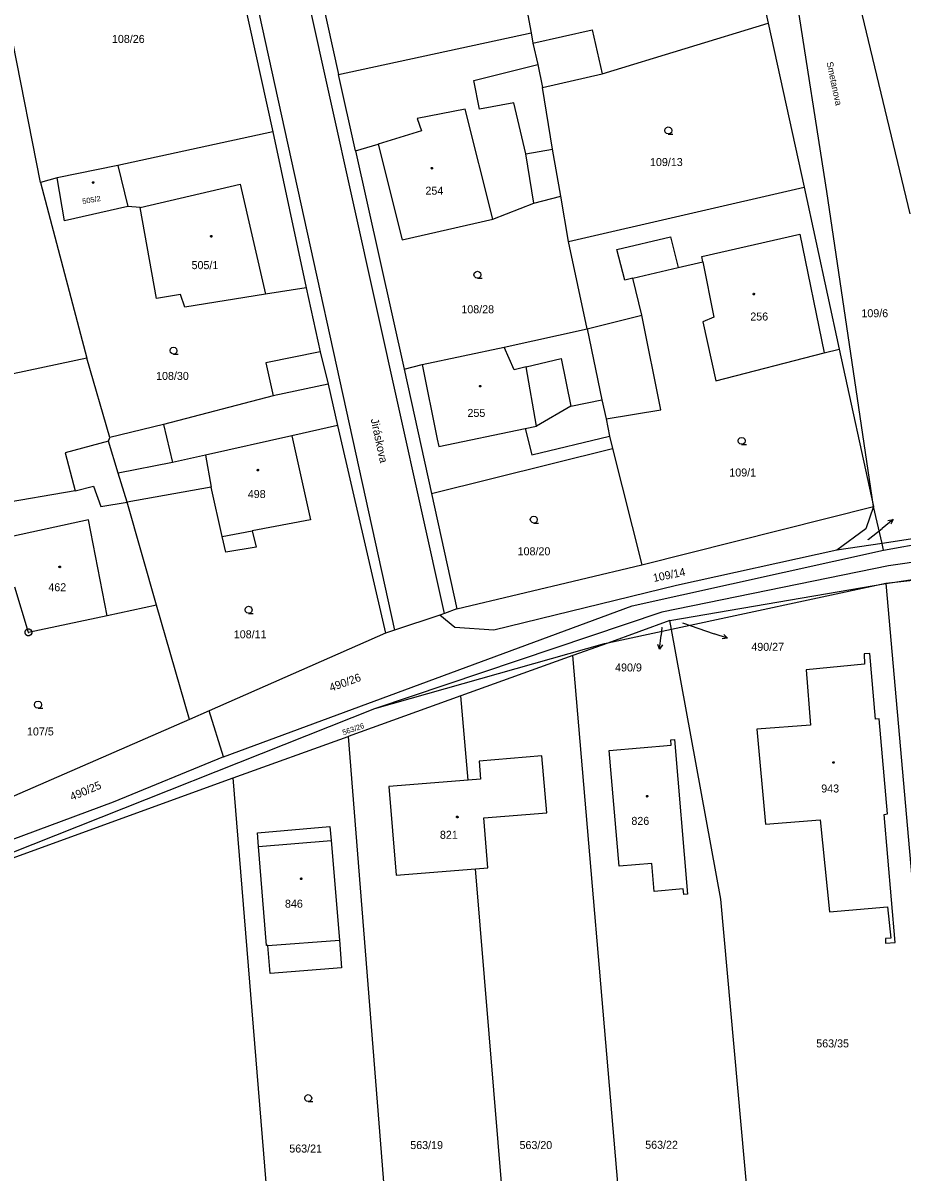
# Model space of a CAD drawing. Extents: x -757994 to -755874, y -1047691 to -1046119.
# Drawn here: x -756569 to -756475.6, y -1047252.5 to -1047130.4 of the extents above; entities that cross this region are included whole.
import ezdxf

# ---------------------------------------------------------------- set-up
doc = ezdxf.new("R2010")
doc.units = 0
doc.layers.add('katastrální mapa', color=7, linetype='Continuous')

msp = doc.modelspace()

# ---------------------------------------------------------------- linework, layer by layer
at = {"layer": 'katastrální mapa'}
for p, q in [((-756524.22, -1047193.08), (-756556.45, -1047047.79)), ((-756561.63, -1047048.85), (-756529.53, -1047194.86)), ((-756550.99, -1047103.27), (-756542.45, -1047141.92)), ((-756493.42, -1047113.76), (-756489.8, -1047130.38)), ((-756483.58, -1047148.25), (-756489.12, -1047112.96)), ((-756540.11, -1047115.02), (-756535.47, -1047135.84)), ((-756516.45, -1047123.58), (-756515.01, -1047131.42)), ((-756481.22, -1047123.75), (-756474.76, -1047150.65)), ((-756507.45, -1047135.75), (-756489.8, -1047130.38)), ((-756489.8, -1047130.38), (-756486, -1047147.79)), ((-756535.47, -1047135.84), (-756515.01, -1047131.42)), ((-756515.01, -1047131.42), (-756514.81, -1047132.51)), ((-756514.81, -1047132.51), (-756508.53, -1047131.08)), ((-756508.53, -1047131.08), (-756507.45, -1047135.75)), ((-756567.16, -1047147.29), (-756570.09, -1047132.35)), ((-756514.81, -1047132.51), (-756514.31, -1047134.76)), ((-756533.66, -1047143.94), (-756535.47, -1047135.84)), ((-756521.08, -1047136.46), (-756514.31, -1047134.76)), ((-756514.31, -1047134.76), (-756513.78, -1047137.22)), ((-756513.78, -1047137.22), (-756507.45, -1047135.75)), ((-756520.49, -1047139.52), (-756521.08, -1047136.46)), ((-756512.72, -1047143.77), (-756513.78, -1047137.22)), ((-756522.01, -1047139.52), (-756527.12, -1047140.5)), ((-756519.08, -1047151.2), (-756522.01, -1047139.52)), ((-756516.86, -1047138.86), (-756520.49, -1047139.52)), ((-756515.57, -1047144.25), (-756516.86, -1047138.86)), ((-756527.12, -1047140.5), (-756526.67, -1047141.83)), ((-756542.45, -1047141.92), (-756558.92, -1047145.5)), ((-756542.45, -1047141.92), (-756538.9, -1047158.49)), ((-756526.67, -1047141.83), (-756531.27, -1047143.22)), ((-756533.66, -1047143.94), (-756531.27, -1047143.22)), ((-756531.27, -1047143.22), (-756528.71, -1047153.41)), ((-756533.66, -1047143.94), (-756528.49, -1047167.15)), ((-756515.57, -1047144.25), (-756512.72, -1047143.77)), ((-756514.71, -1047149.51), (-756515.57, -1047144.25)), ((-756511.85, -1047148.75), (-756512.72, -1047143.77)), ((-756558.92, -1047145.5), (-756565.4, -1047146.8)), ((-756558.92, -1047145.5), (-756557.88, -1047149.85)), ((-756565.4, -1047146.8), (-756567.16, -1047147.29)), ((-756564.6, -1047151.38), (-756565.4, -1047146.8)), ((-756567.16, -1047147.29), (-756562.24, -1047165.98)), ((-756556.56, -1047149.96), (-756545.92, -1047147.49)), ((-756545.92, -1047147.49), (-756543.24, -1047159.18)), ((-756511.04, -1047153.57), (-756486, -1047147.79)), ((-756486, -1047147.79), (-756482.25, -1047165)), ((-756514.71, -1047149.51), (-756511.85, -1047148.75)), ((-756511.04, -1047153.57), (-756511.85, -1047148.75)), ((-756478.61, -1047181.72), (-756483.58, -1047148.25)), ((-756557.88, -1047149.85), (-756564.6, -1047151.38)), ((-756556.56, -1047149.96), (-756557.88, -1047149.85)), ((-756554.82, -1047159.62), (-756556.56, -1047149.96)), ((-756519.08, -1047151.2), (-756514.71, -1047149.51)), ((-756528.71, -1047153.41), (-756519.08, -1047151.2)), ((-756496.86, -1047155.17), (-756486.46, -1047152.81)), ((-756486.46, -1047152.81), (-756483.85, -1047165.41)), ((-756509.04, -1047162.84), (-756511.04, -1047153.57)), ((-756505.88, -1047154.44), (-756500.2, -1047153.08)), ((-756500.2, -1047153.08), (-756499.37, -1047156.34)), ((-756505.05, -1047157.67), (-756505.88, -1047154.44)), ((-756496.75, -1047155.73), (-756496.86, -1047155.17)), ((-756504.21, -1047157.47), (-756499.37, -1047156.34)), ((-756499.37, -1047156.34), (-756496.75, -1047155.73)), ((-756496.75, -1047155.73), (-756495.59, -1047161.61)), ((-756504.21, -1047157.47), (-756505.05, -1047157.67)), ((-756503.25, -1047161.4), (-756504.21, -1047157.47)), ((-756538.9, -1047158.49), (-756543.24, -1047159.18)), ((-756538.9, -1047158.49), (-756537.44, -1047165.3)), ((-756552.29, -1047159.21), (-756554.82, -1047159.62)), ((-756551.8, -1047160.54), (-756552.29, -1047159.21)), ((-756543.24, -1047159.18), (-756551.8, -1047160.54)), ((-756509.04, -1047162.84), (-756503.25, -1047161.4)), ((-756501.23, -1047171.46), (-756503.25, -1047161.4)), ((-756495.59, -1047161.61), (-756496.77, -1047162.1)), ((-756496.77, -1047162.1), (-756495.38, -1047168.38)), ((-756517.88, -1047164.8), (-756509.04, -1047162.84)), ((-756509.04, -1047162.84), (-756507.48, -1047170.41)), ((-756526.59, -1047166.64), (-756517.88, -1047164.8)), ((-756516.8, -1047167.2), (-756517.88, -1047164.8)), ((-756483.85, -1047165.41), (-756482.25, -1047165)), ((-756482.25, -1047165), (-756478.61, -1047181.72)), ((-756562.24, -1047165.98), (-756575.35, -1047168.74)), ((-756559.79, -1047174.38), (-756562.24, -1047165.98)), ((-756537.44, -1047165.3), (-756543.2, -1047166.46)), ((-756543.2, -1047166.46), (-756542.42, -1047169.97)), ((-756537.44, -1047165.3), (-756536.58, -1047168.73)), ((-756515.55, -1047166.9), (-756511.8, -1047166.01)), ((-756511.8, -1047166.01), (-756510.78, -1047171.08)), ((-756495.38, -1047168.38), (-756483.85, -1047165.41)), ((-756528.49, -1047167.15), (-756526.59, -1047166.64)), ((-756528.49, -1047167.15), (-756525.58, -1047180.35)), ((-756526.59, -1047166.64), (-756524.99, -1047174.56)), ((-756515.55, -1047166.9), (-756516.8, -1047167.2)), ((-756514.44, -1047173.18), (-756515.55, -1047166.9)), ((-756536.58, -1047168.73), (-756542.42, -1047169.97)), ((-756536.58, -1047168.73), (-756535.57, -1047173.12)), ((-756542.42, -1047169.97), (-756554.08, -1047173.02)), ((-756510.78, -1047171.08), (-756514.44, -1047173.18)), ((-756510.78, -1047171.08), (-756507.48, -1047170.41)), ((-756507.48, -1047170.41), (-756507.02, -1047172.42)), ((-756507.02, -1047172.42), (-756501.23, -1047171.46)), ((-756507.02, -1047172.42), (-756506.67, -1047174.26)), ((-756554.08, -1047173.02), (-756559.79, -1047174.38)), ((-756554.08, -1047173.02), (-756553.14, -1047177.07)), ((-756535.57, -1047173.12), (-756540.45, -1047174.22)), ((-756535.57, -1047173.12), (-756530.5, -1047195.18)), ((-756524.83, -1047175.37), (-756515.65, -1047173.43)), ((-756515.65, -1047173.43), (-756514.44, -1047173.18)), ((-756515.65, -1047173.43), (-756514.93, -1047176.24)), ((-756559.92, -1047174.8), (-756564.52, -1047176.03)), ((-756559.92, -1047174.8), (-756559.79, -1047174.38)), ((-756558.89, -1047178.17), (-756559.92, -1047174.8)), ((-756540.45, -1047174.22), (-756549.63, -1047176.28)), ((-756540.45, -1047174.22), (-756538.45, -1047183.16)), ((-756524.99, -1047174.56), (-756524.83, -1047175.37)), ((-756514.93, -1047176.24), (-756506.67, -1047174.26)), ((-756506.67, -1047174.26), (-756506.34, -1047175.56)), ((-756564.52, -1047176.03), (-756563.47, -1047180.07)), ((-756525.58, -1047180.35), (-756506.34, -1047175.56)), ((-756506.34, -1047175.56), (-756503.24, -1047187.93)), ((-756553.14, -1047177.07), (-756558.89, -1047178.17)), ((-756549.63, -1047176.28), (-756553.14, -1047177.07)), ((-756549.63, -1047176.28), (-756549.01, -1047179.66)), ((-756557.94, -1047181.26), (-756558.89, -1047178.17)), ((-756563.47, -1047180.07), (-756561.53, -1047179.56)), ((-756561.53, -1047179.56), (-756560.75, -1047181.74)), ((-756549.01, -1047179.66), (-756557.94, -1047181.26)), ((-756547.83, -1047184.9), (-756549.01, -1047179.66)), ((-756563.47, -1047180.07), (-756581.5, -1047183.16)), ((-756525.58, -1047180.35), (-756522.9, -1047192.59)), ((-756446.07, -1047180.81), (-756477.7, -1047185.65)), ((-756477.54, -1047186.35), (-756446.07, -1047180.81)), ((-756560.75, -1047181.74), (-756557.94, -1047181.26)), ((-756554.81, -1047192.22), (-756557.94, -1047181.26)), ((-756503.24, -1047187.93), (-756478.61, -1047181.72)), ((-756478.61, -1047181.72), (-756479.44, -1047184.1)), ((-756477.7, -1047185.65), (-756478.61, -1047181.72)), ((-756431.54, -1047181.25), (-756477.02, -1047188.04)), ((-756562.07, -1047183.15), (-756570.85, -1047185.07)), ((-756560.07, -1047193.33), (-756562.07, -1047183.15)), ((-756538.45, -1047183.16), (-756544.65, -1047184.31)), ((-756476.53, -1047183.11), (-756477.7, -1047184.05)), ((-756547.83, -1047184.9), (-756544.65, -1047184.31)), ((-756544.65, -1047184.31), (-756544.22, -1047186.04)), ((-756479.44, -1047184.1), (-756482.5, -1047186.38)), ((-756479.18, -1047185.24), (-756477.7, -1047184.05)), ((-756547.44, -1047186.59), (-756547.83, -1047184.9)), ((-756477.7, -1047185.65), (-756482.5, -1047186.38)), ((-756477.54, -1047186.35), (-756477.7, -1047185.65)), ((-756544.22, -1047186.04), (-756547.44, -1047186.59)), ((-756504.27, -1047192.28), (-756477.54, -1047186.35)), ((-756482.5, -1047186.38), (-756499.54, -1047190.11)), ((-756522.9, -1047192.59), (-756503.24, -1047187.93)), ((-756477.02, -1047188.04), (-756501.12, -1047192.94)), ((-756477.31, -1047189.92), (-756464.18, -1047187.91)), ((-756464.1, -1047188.38), (-756477.31, -1047189.92)), ((-756568.44, -1047195.1), (-756569.87, -1047190.3)), ((-756499.54, -1047190.11), (-756518.96, -1047194.86)), ((-756500.26, -1047193.84), (-756477.31, -1047189.92)), ((-756477.31, -1047189.92), (-756500.09, -1047194.78)), ((-756560.07, -1047193.33), (-756568.44, -1047195.1)), ((-756554.81, -1047192.22), (-756560.07, -1047193.33)), ((-756551.33, -1047204.37), (-756554.81, -1047192.22)), ((-756547.69, -1047208.31), (-756504.27, -1047192.28)), ((-756501.12, -1047192.94), (-756531.64, -1047203.23)), ((-756524.72, -1047193.26), (-756529.53, -1047194.86)), ((-756524.22, -1047193.08), (-756524.72, -1047193.26)), ((-756523.12, -1047194.59), (-756524.72, -1047193.26)), ((-756522.9, -1047192.59), (-756524.22, -1047193.08)), ((-756500.26, -1047193.84), (-756506.87, -1047196.23)), ((-756500.09, -1047194.78), (-756500.26, -1047193.84)), ((-756498.93, -1047194.08), (-756495.56, -1047195.24)), ((-756568.47, -1047195.1), (-756568.41, -1047195.1)), ((-756530.5, -1047195.18), (-756549.22, -1047203.44)), ((-756529.53, -1047194.86), (-756530.5, -1047195.18)), ((-756518.96, -1047194.86), (-756523.12, -1047194.59)), ((-756500.09, -1047194.78), (-756506.87, -1047196.23)), ((-756501.35, -1047196.9), (-756501.2, -1047195.41)), ((-756501.12, -1047194.58), (-756501.2, -1047195.41)), ((-756494.84, -1047223.43), (-756500.09, -1047194.78)), ((-756494.14, -1047195.73), (-756495.56, -1047195.24)), ((-756507.23, -1047196.31), (-756531.64, -1047203.23)), ((-756506.87, -1047196.23), (-756510.56, -1047197.57)), ((-756506.87, -1047196.23), (-756507.23, -1047196.31)), ((-756510.56, -1047197.57), (-756522.46, -1047201.84)), ((-756503.36, -1047282.2), (-756510.56, -1047197.57)), ((-756522.46, -1047201.84), (-756534.45, -1047206.15)), ((-756521.71, -1047210.8), (-756522.46, -1047201.84)), ((-756531.64, -1047203.23), (-756570.37, -1047218.58)), ((-756549.22, -1047203.44), (-756551.33, -1047204.37)), ((-756547.69, -1047208.31), (-756549.22, -1047203.44)), ((-756551.33, -1047204.37), (-756571.3, -1047213.07)), ((-756546.68, -1047210.54), (-756534.45, -1047206.15)), ((-756534.45, -1047206.15), (-756528.22, -1047284.55)), ((-756500.17, -1047206.52), (-756499.76, -1047206.48)), ((-756500.12, -1047207.09), (-756500.17, -1047206.52)), ((-756499.76, -1047206.48), (-756498.39, -1047222.92)), ((-756506.7, -1047207.66), (-756500.12, -1047207.09)), ((-756505.64, -1047219.92), (-756506.7, -1047207.66)), ((-756547.69, -1047208.31), (-756559.42, -1047213.15)), ((-756513.86, -1047208.21), (-756520.54, -1047208.77)), ((-756520.54, -1047208.77), (-756520.4, -1047210.7)), ((-756513.35, -1047214.27), (-756513.86, -1047208.21)), ((-756576.29, -1047221.29), (-756546.68, -1047210.54)), ((-756540.56, -1047285.72), (-756546.68, -1047210.54)), ((-756521.71, -1047210.8), (-756530.12, -1047211.48)), ((-756530.12, -1047211.48), (-756529.35, -1047220.89)), ((-756520.4, -1047210.7), (-756521.71, -1047210.8)), ((-756559.42, -1047213.15), (-756575.65, -1047219.15)), ((-756520.04, -1047214.81), (-756513.35, -1047214.27)), ((-756519.61, -1047220.13), (-756520.04, -1047214.81)), ((-756544.1, -1047216.38), (-756536.39, -1047215.73)), ((-756543.98, -1047217.86), (-756544.1, -1047216.38)), ((-756536.39, -1047215.73), (-756536.25, -1047217.22)), ((-756543.98, -1047217.86), (-756536.25, -1047217.22)), ((-756536.25, -1047217.22), (-756535.37, -1047227.78)), ((-756543.15, -1047228.36), (-756543.98, -1047217.86)), ((-756529.35, -1047220.89), (-756520.92, -1047220.23)), ((-756520.92, -1047220.23), (-756519.61, -1047220.13)), ((-756515.65, -1047283.36), (-756520.92, -1047220.23)), ((-756502.18, -1047219.66), (-756505.64, -1047219.92)), ((-756501.92, -1047222.62), (-756502.18, -1047219.66)), ((-756498.83, -1047222.36), (-756501.92, -1047222.62)), ((-756498.78, -1047222.96), (-756498.83, -1047222.36)), ((-756498.39, -1047222.92), (-756498.78, -1047222.96)), ((-756491.19, -1047264.16), (-756494.84, -1047223.43)), ((-756542.99, -1047228.35), (-756543.15, -1047228.36)), ((-756542.99, -1047228.35), (-756535.37, -1047227.78)), ((-756542.76, -1047231.35), (-756542.99, -1047228.35)), ((-756535.37, -1047227.78), (-756535.17, -1047230.73)), ((-756535.17, -1047230.73), (-756542.76, -1047231.35))]:
    msp.add_line(p, q, dxfattribs=at)
for points in [[(-756500.42, -1047142.15), (-756500.61, -1047142.1), (-756500.75, -1047141.97), (-756500.8, -1047141.78), (-756500.75, -1047141.6), (-756500.61, -1047141.46), (-756500.43, -1047141.41), (-756500.24, -1047141.46), (-756500.1, -1047141.6), (-756500.06, -1047141.79), (-756500.1, -1047141.98), (-756500.24, -1047142.11), (-756500.43, -1047142.16), (-756499.93, -1047142.16)], [(-756520.7, -1047157.47), (-756520.89, -1047157.42), (-756521.02, -1047157.28), (-756521.08, -1047157.1), (-756521.02, -1047156.92), (-756520.89, -1047156.78), (-756520.71, -1047156.73), (-756520.52, -1047156.78), (-756520.39, -1047156.92), (-756520.34, -1047157.11), (-756520.39, -1047157.29), (-756520.52, -1047157.43), (-756520.71, -1047157.48), (-756520.21, -1047157.48)], [(-756553.01, -1047165.54), (-756553.2, -1047165.49), (-756553.34, -1047165.36), (-756553.39, -1047165.17), (-756553.34, -1047164.99), (-756553.2, -1047164.85), (-756553.02, -1047164.8), (-756552.83, -1047164.85), (-756552.7, -1047164.99), (-756552.65, -1047165.18), (-756552.7, -1047165.37), (-756552.83, -1047165.5), (-756553.02, -1047165.55), (-756552.52, -1047165.55)], [(-756492.62, -1047175.12), (-756492.81, -1047175.07), (-756492.95, -1047174.94), (-756492.99, -1047174.75), (-756492.95, -1047174.57), (-756492.81, -1047174.43), (-756492.62, -1047174.38), (-756492.44, -1047174.43), (-756492.3, -1047174.57), (-756492.26, -1047174.76), (-756492.3, -1047174.95), (-756492.44, -1047175.08), (-756492.63, -1047175.13), (-756492.13, -1047175.13)], [(-756514.72, -1047183.49), (-756514.91, -1047183.44), (-756515.04, -1047183.3), (-756515.1, -1047183.12), (-756515.04, -1047182.94), (-756514.91, -1047182.8), (-756514.73, -1047182.75), (-756514.54, -1047182.8), (-756514.41, -1047182.94), (-756514.35, -1047183.12), (-756514.41, -1047183.32), (-756514.54, -1047183.45), (-756514.73, -1047183.5), (-756514.23, -1047183.5)], [(-756477.08, -1047183.23), (-756476.53, -1047183.11), (-756476.76, -1047183.62)], [(-756477.31, -1047189.92), (-756471.08, -1047260.48), (-756491.19, -1047264.16)], [(-756545.03, -1047193.07), (-756545.22, -1047193.02), (-756545.35, -1047192.89), (-756545.41, -1047192.7), (-756545.35, -1047192.51), (-756545.22, -1047192.38), (-756545.04, -1047192.33), (-756544.85, -1047192.38), (-756544.72, -1047192.51), (-756544.67, -1047192.71), (-756544.72, -1047192.9), (-756544.85, -1047193.03), (-756545.04, -1047193.08), (-756544.54, -1047193.08)], [(-756494.53, -1047195.33), (-756494.14, -1047195.73), (-756494.7, -1047195.8)], [(-756501.05, -1047196.43), (-756501.35, -1047196.9), (-756501.55, -1047196.38)], [(-756567.41, -1047203.15), (-756567.6, -1047203.1), (-756567.74, -1047202.97), (-756567.79, -1047202.78), (-756567.74, -1047202.6), (-756567.6, -1047202.46), (-756567.42, -1047202.41), (-756567.23, -1047202.46), (-756567.1, -1047202.6), (-756567.05, -1047202.79), (-756567.1, -1047202.98), (-756567.23, -1047203.11), (-756567.42, -1047203.16), (-756566.92, -1047203.16)], [(-756538.69, -1047244.94), (-756538.88, -1047244.89), (-756539.01, -1047244.75), (-756539.07, -1047244.57), (-756539.01, -1047244.39), (-756538.88, -1047244.25), (-756538.7, -1047244.2), (-756538.51, -1047244.25), (-756538.38, -1047244.39), (-756538.33, -1047244.58), (-756538.38, -1047244.76), (-756538.51, -1047244.9), (-756538.7, -1047244.95), (-756538.2, -1047244.95)]]:
    msp.add_lwpolyline(points, dxfattribs=at)
for points in [[(-756525.56, -1047145.71), (-756525.51, -1047145.72), (-756525.49, -1047145.76), (-756525.48, -1047145.79), (-756525.49, -1047145.84), (-756525.53, -1047145.87), (-756525.56, -1047145.88), (-756525.6, -1047145.86), (-756525.64, -1047145.83), (-756525.65, -1047145.79), (-756525.64, -1047145.75), (-756525.6, -1047145.71)], [(-756561.54, -1047147.23), (-756561.49, -1047147.24), (-756561.47, -1047147.28), (-756561.46, -1047147.31), (-756561.47, -1047147.36), (-756561.51, -1047147.39), (-756561.54, -1047147.4), (-756561.59, -1047147.38), (-756561.61, -1047147.35), (-756561.62, -1047147.31), (-756561.61, -1047147.27), (-756561.58, -1047147.23)], [(-756549, -1047152.94), (-756548.95, -1047152.95), (-756548.93, -1047152.99), (-756548.92, -1047153.02), (-756548.93, -1047153.07), (-756548.97, -1047153.1), (-756549, -1047153.11), (-756549.04, -1047153.09), (-756549.08, -1047153.06), (-756549.09, -1047153.02), (-756549.08, -1047152.98), (-756549.03, -1047152.94)], [(-756491.33, -1047159.08), (-756491.28, -1047159.09), (-756491.25, -1047159.13), (-756491.24, -1047159.16), (-756491.25, -1047159.21), (-756491.29, -1047159.24), (-756491.33, -1047159.25), (-756491.38, -1047159.23), (-756491.41, -1047159.2), (-756491.42, -1047159.16), (-756491.41, -1047159.12), (-756491.36, -1047159.08)], [(-756520.42, -1047168.86), (-756520.37, -1047168.87), (-756520.35, -1047168.91), (-756520.34, -1047168.94), (-756520.35, -1047168.98), (-756520.39, -1047169.02), (-756520.42, -1047169.02), (-756520.47, -1047169.01), (-756520.5, -1047168.98), (-756520.51, -1047168.94), (-756520.5, -1047168.9), (-756520.46, -1047168.86)], [(-756544.05, -1047177.77), (-756544, -1047177.78), (-756543.98, -1047177.83), (-756543.97, -1047177.86), (-756543.98, -1047177.91), (-756544.02, -1047177.94), (-756544.05, -1047177.95), (-756544.1, -1047177.93), (-756544.12, -1047177.9), (-756544.14, -1047177.86), (-756544.12, -1047177.82), (-756544.09, -1047177.78)], [(-756565.11, -1047188.05), (-756565.06, -1047188.07), (-756565.03, -1047188.11), (-756565.02, -1047188.14), (-756565.03, -1047188.19), (-756565.08, -1047188.22), (-756565.11, -1047188.23), (-756565.16, -1047188.21), (-756565.19, -1047188.18), (-756565.2, -1047188.14), (-756565.19, -1047188.1), (-756565.15, -1047188.06)], [(-756568.35, -1047194.74), (-756568.17, -1047194.84), (-756568.08, -1047195.01), (-756568.08, -1047195.2), (-756568.17, -1047195.37), (-756568.35, -1047195.47), (-756568.54, -1047195.47), (-756568.71, -1047195.37), (-756568.8, -1047195.2), (-756568.8, -1047195.01), (-756568.71, -1047194.84), (-756568.54, -1047194.74)], [(-756476.3, -1047228.03), (-756477.49, -1047214.44), (-756477.14, -1047214.36), (-756478.03, -1047204.28), (-756478.39, -1047204.31), (-756479, -1047197.34), (-756479.6, -1047197.39), (-756479.56, -1047198.48), (-756485.79, -1047199.09), (-756485.31, -1047204.95), (-756491.01, -1047205.38), (-756490.1, -1047215.47), (-756484.29, -1047215), (-756483.29, -1047224.77), (-756477.14, -1047224.26), (-756476.78, -1047227.57), (-756477.35, -1047227.63), (-756477.35, -1047228.12)], [(-756482.86, -1047208.84), (-756482.81, -1047208.85), (-756482.78, -1047208.89), (-756482.77, -1047208.92), (-756482.78, -1047208.97), (-756482.83, -1047209), (-756482.86, -1047209.01), (-756482.91, -1047208.99), (-756482.94, -1047208.96), (-756482.95, -1047208.92), (-756482.94, -1047208.88), (-756482.9, -1047208.84)], [(-756502.69, -1047212.43), (-756502.64, -1047212.44), (-756502.61, -1047212.48), (-756502.6, -1047212.51), (-756502.61, -1047212.55), (-756502.66, -1047212.59), (-756502.69, -1047212.6), (-756502.73, -1047212.58), (-756502.76, -1047212.55), (-756502.77, -1047212.51), (-756502.76, -1047212.47), (-756502.72, -1047212.43)], [(-756522.85, -1047214.62), (-756522.8, -1047214.64), (-756522.77, -1047214.68), (-756522.76, -1047214.71), (-756522.77, -1047214.75), (-756522.82, -1047214.79), (-756522.85, -1047214.79), (-756522.9, -1047214.78), (-756522.93, -1047214.75), (-756522.94, -1047214.71), (-756522.93, -1047214.67), (-756522.89, -1047214.63)], [(-756539.44, -1047221.19), (-756539.39, -1047221.2), (-756539.36, -1047221.24), (-756539.35, -1047221.27), (-756539.36, -1047221.32), (-756539.41, -1047221.35), (-756539.44, -1047221.36), (-756539.48, -1047221.34), (-756539.51, -1047221.31), (-756539.52, -1047221.27), (-756539.51, -1047221.23), (-756539.47, -1047221.19)]]:
    msp.add_lwpolyline(points, close=True, dxfattribs=at)

# ---------------------------------------------------------------- texts
for s, height, p in [('108/26', 0.85, (-756559.56, -1047132.48)), ('109/13', 0.85, (-756502.37, -1047145.56)), ('254', 0.85, (-756526.24, -1047148.6)), ('505/1', 0.85, (-756551.1, -1047156.51)), ('108/28', 0.85, (-756522.42, -1047161.2)), ('256', 0.85, (-756491.71, -1047161.97)), ('109/6', 0.85, (-756479.9, -1047161.62)), ('108/30', 0.85, (-756554.87, -1047168.28)), ('255', 0.85, (-756521.77, -1047172.21)), ('109/1', 0.85, (-756493.94, -1047178.54)), ('498', 0.85, (-756545.12, -1047180.83)), ('108/20', 0.85, (-756516.44, -1047186.91)), ('109/25', 0.05, (-756479.3, -1047185.24)), ('462', 0.85, (-756566.32, -1047190.73)), ('490/9', 0.05, (-756501.22, -1047194.58)), ('490/27', 0.05, (-756499.05, -1047194.08)), ('108/11', 0.85, (-756546.61, -1047195.73)), ('490/27', 0.85, (-756491.6, -1047197.06)), ('490/9', 0.85, (-756506.08, -1047199.25)), ('107/5', 0.85, (-756568.59, -1047206.05)), ('943', 0.85, (-756484.17, -1047212.11)), ('826', 0.85, (-756504.35, -1047215.55)), ('821', 0.85, (-756524.7, -1047217.03)), ('846', 0.85, (-756541.17, -1047224.35)), ('563/35', 0.85, (-756484.7, -1047239.19)), ('563/21', 0.85, (-756540.71, -1047250.36)), ('563/19', 0.85, (-756527.85, -1047249.99)), ('563/20', 0.85, (-756516.24, -1047249.99)), ('563/22', 0.85, (-756502.88, -1047249.96))]:
    msp.add_text(s, height=height, dxfattribs=at).set_placement(p)
for s, height, rotation, p in [('Smetanova', 0.7, 282.0671, (-756483.62, -1047134.56)), ('505/2', 0.57, 9.7976, (-756562.66, -1047149.6)), ('Jiráskova', 0.85, 282.239, (-756532.07, -1047172.47)), ('109/14', 0.85, 11.4592, (-756501.96, -1047189.75)), ('490/26', 0.85, 19.8816, (-756536.28, -1047201.4)), ('563/26', 0.57, 19.1368, (-756534.95, -1047206.03)), ('490/25', 0.85, 22.861, (-756563.81, -1047213))]:
    msp.add_text(s, height=height, rotation=rotation, dxfattribs=at).set_placement(p)

doc.saveas('drawing.dxf')
